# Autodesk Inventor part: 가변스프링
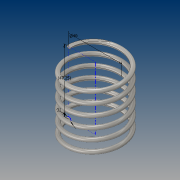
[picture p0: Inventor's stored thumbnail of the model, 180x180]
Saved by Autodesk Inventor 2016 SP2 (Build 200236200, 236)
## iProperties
Created: 2018-02
Part Number: 가변스프링
Material: 스테인레스 스틸
Document SubType Name: Modeling
Designer: Administrator
Density: 8 g/cm^3
Appearance: 반연마
Author: Administrator
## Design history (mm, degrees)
sketch "스케치1"
  geometry: L1 (0, 0)-(-20, 0); L2 (-20, 0)-(-20, 47.25); L3 (-20, 47.25)-(0, 47.25); L4 (0, 47.25)-(0, 0); C1 r 1.5 at (-20, 0)
  constraints: 8 end point, 2 parallel, 1 centre point, 1 coincident, 1 horizontal, 1 perpendicular
  dimensions: "d0" = 47.25 distance of L1.end L2.end (derived); "d1" = 40 diameter of L2 L4; "d2" = 3 diameter of C1
feature "코일1" pitch "d3" = 10; turns "d5" = 6; dims "d4" = 47.25 (= d0), "d6" = 0, angle "d7" = 90 deg, angle "d8" = 90 deg, "d9" = 0, "d10" = 0
sketch "스케치2"
  geometry: L1 (21.5, 0)-(18.5, 0) reference; 1 further point
  constraints: 1 horizontal alignment
extrude "돌출1" cut sketch "스케치2" distance "d11" = 10; taper "d12" = 0 deg
node "작업 평면1"
sketch "스케치3"
  geometry: L1 (-1.5, 0)-(1.5, 0) reference; 1 further point
  constraints: 1 horizontal alignment
extrude "돌출2" cut sketch "스케치3" distance "d14" = 10; taper "d15" = 0 deg
node "솔리드1"
node "절단 모서리 투영1"
node "절단 모서리 투영2"
other parameters: "d13" = 90 deg
